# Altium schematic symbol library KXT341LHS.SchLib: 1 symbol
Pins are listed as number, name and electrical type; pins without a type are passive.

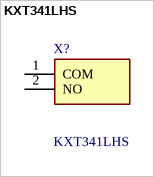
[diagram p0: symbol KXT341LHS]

## KXT341LHS
designator X?
Keypad Switch, 1 Switches, SPST, Momentary-tactile, 0.02A, 15VDC, 3.92N, Solder Terminal, Surface Mount-straight; Manufacturer_Name: C & K COMPONENTS; Geometry.Height: 0.7mm
footprint KXT341LHS
pins: 1 COM, 2 NO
